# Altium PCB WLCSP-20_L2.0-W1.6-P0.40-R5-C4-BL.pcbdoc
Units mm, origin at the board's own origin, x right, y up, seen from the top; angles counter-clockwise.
Board outline 14.76 x 14.63 mm, 2 copper layers (Top Layer, Bottom Layer), stack 0 mm thick; 1 components, 0 nets, 20 pads, 0 vias.
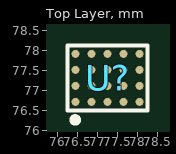
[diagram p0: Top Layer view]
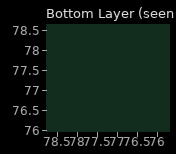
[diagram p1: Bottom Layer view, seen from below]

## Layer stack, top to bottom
Top Layer: signal copper (thickness not stored)
Bottom Layer: signal copper (thickness not stored)

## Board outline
84.61,69.85 69.85,69.85 69.85,84.485 84.61,84.485

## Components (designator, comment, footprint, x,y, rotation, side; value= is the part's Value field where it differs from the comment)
U? "" WLCSP-20_L2.0-W1.6-P0.40-R5-C4-BL 77.26,77.325 r0 top

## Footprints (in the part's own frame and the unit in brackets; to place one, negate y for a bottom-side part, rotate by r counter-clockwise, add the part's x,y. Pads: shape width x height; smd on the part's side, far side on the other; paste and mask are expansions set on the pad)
WLCSP-20_L2.0-W1.6-P0.40-R5-C4-BL [mm]
  round 0.2 smd paste+0 mask+0.05: A1(-0.8,-0.6) A2(-0.8,-0.2) A3(-0.8,0.2) A4(-0.8,0.6) B1(-0.4,-0.6) B2(-0.4,-0.2) B3(-0.4,0.2) B4(-0.4,0.6) C1(0,-0.6) C2(0,-0.2) C3(0,0.2) C4(0,0.6) D1(0.4,-0.6) D2(0.4,-0.2) D3(0.4,0.2) D4(0.4,0.6) E1(0.8,-0.6) E2(0.8,-0.2) E3(0.8,0.2) E4(0.8,0.6)
  silkscreen extent -1,-1.12 1,0.81

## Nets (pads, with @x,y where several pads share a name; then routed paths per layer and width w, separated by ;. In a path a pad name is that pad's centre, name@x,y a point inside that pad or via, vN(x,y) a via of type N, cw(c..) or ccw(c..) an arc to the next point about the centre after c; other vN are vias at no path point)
pads on no net: U?.A1 U?.A2 U?.A3 U?.A4 U?.B1 U?.B2 U?.B3 U?.B4 U?.C1 U?.C2 U?.C3 U?.C4 U?.D1 U?.D2 U?.D3 U?.D4 U?.E1 U?.E2 U?.E3 U?.E4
